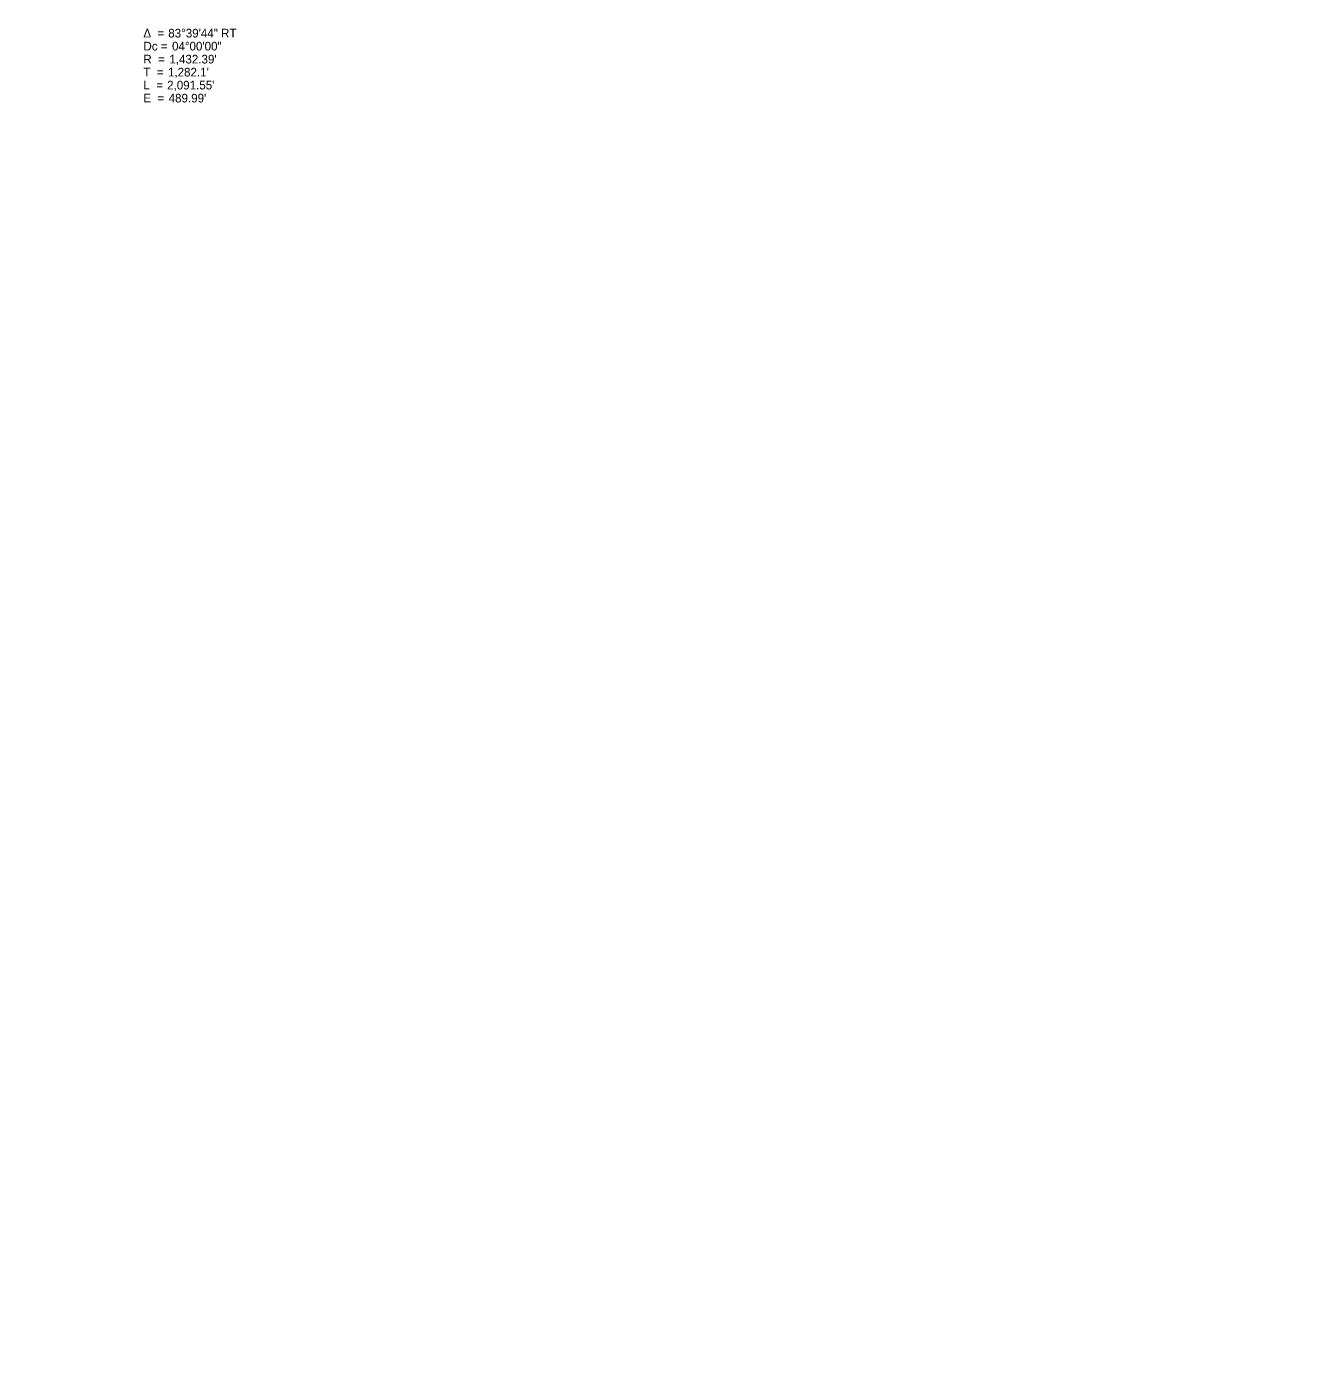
# Model space of a CAD drawing. Extents: x 1454426 to 1455277, y 587472 to 590476.
# Drawn here: x 1454844.3 to 1455257.6, y 587916.7 to 588347.4 of the extents above; entities that cross this region are included whole.
import ezdxf

# ---------------------------------------------------------------- set-up
doc = ezdxf.new("R2010")
doc.units = 0
for name, color, linetype in [('GT_Target_Soil_Boring', 7, 'Continuous'), ('PV_P_Saw_Cut_Line', 7, 'Continuous'), ('RD_P_Wall', 7, 'Continuous'), ('RS_Raster2', 7, 'Continuous'), ('SC_Scratch4', 7, 'Continuous')]:
    doc.layers.add(name, color=color, linetype=linetype)

msp = doc.modelspace()

# ---------------------------------------------------------------- linework, layer by layer
at = {"layer": 'GT_Target_Soil_Boring'}
msp.add_arc((1455863.38, 588770.51), 1432.39, 161.3175, 244.97965, dxfattribs=at)
at = {"layer": 'PV_P_Saw_Cut_Line'}
msp.add_arc((1455863.38, 588770.51), 1432.39, 161.3175, 244.97965, dxfattribs=at)

# ---------------------------------------------------------------- texts
at = {"layer": 'RD_P_Wall'}
for s, p in [('Δ  = ', (1454882.02, 588343.94)), ('83°39\'44" RT', (1454890.04, 588343.94)), ('Dc = ', (1454882.02, 588339.74)), ('04°00\'00"', (1454891.26, 588339.74)), ('R  = ', (1454882.02, 588335.54)), ("1,432.39'", (1454890.39, 588335.54)), ('T  = ', (1454882.02, 588331.34)), ("1,282.1'", (1454889.95, 588331.34)), ('L  = ', (1454882.02, 588327.14)), ("2,091.55'", (1454889.67, 588327.14)), ('E  = ', (1454882.02, 588322.94)), ("489.99'", (1454890.17, 588322.94))]:
    msp.add_text(s, height=2.8, dxfattribs=at).set_placement(p)
at = {"layer": 'RS_Raster2'}
for s, p in [('Δ  = ', (1454882.02, 588343.94)), ('83°39\'44" RT', (1454890.04, 588343.94)), ('Dc = ', (1454882.02, 588339.74)), ('04°00\'00"', (1454891.26, 588339.74)), ('R  = ', (1454882.02, 588335.54)), ("1,432.39'", (1454890.39, 588335.54)), ('T  = ', (1454882.02, 588331.34)), ("1,282.1'", (1454889.95, 588331.34)), ('L  = ', (1454882.02, 588327.14)), ("2,091.55'", (1454889.67, 588327.14)), ('E  = ', (1454882.02, 588322.94)), ("489.99'", (1454890.17, 588322.94))]:
    msp.add_text(s, height=2.8, dxfattribs=at).set_placement(p)
at = {"layer": 'SC_Scratch4'}
for s, p in [('Δ  = ', (1454882.02, 588343.94)), ('83°39\'44" RT', (1454890.04, 588343.94)), ('Dc = ', (1454882.02, 588339.74)), ('04°00\'00"', (1454891.26, 588339.74)), ('R  = ', (1454882.02, 588335.54)), ("1,432.39'", (1454890.39, 588335.54)), ('T  = ', (1454882.02, 588331.34)), ("1,282.1'", (1454889.95, 588331.34)), ('L  = ', (1454882.02, 588327.14)), ("2,091.55'", (1454889.67, 588327.14)), ('E  = ', (1454882.02, 588322.94)), ("489.99'", (1454890.17, 588322.94))]:
    msp.add_text(s, height=2.8, dxfattribs=at).set_placement(p)

doc.saveas('drawing.dxf')
